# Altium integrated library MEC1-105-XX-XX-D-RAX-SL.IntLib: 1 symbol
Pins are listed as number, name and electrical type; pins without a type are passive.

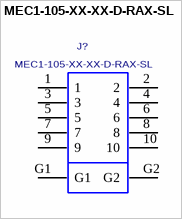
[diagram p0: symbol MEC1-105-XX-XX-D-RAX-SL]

## MEC1-105-XX-XX-D-RAX-SL
designator J?
1MM MEC1-RA ASSEMBLY.; MANUFACTURER: SAMTEC
footprint MEC1-105-XX-XX-D-RAX-SL
pins: 1, 2, 3, 4, 5, 6, 7, 8, 9, 10, G1, G2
